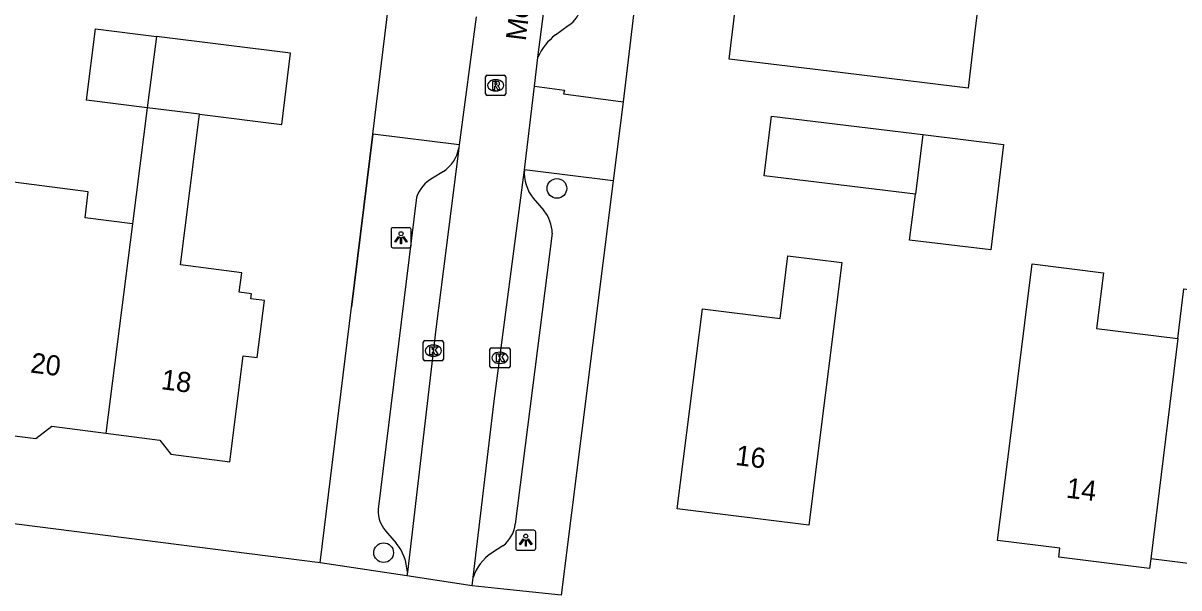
# Model space of a CAD drawing. Extents: x 161258 to 161838, y 380836 to 381727.
# Drawn here: x 161604.4 to 161661.9, y 381360.9 to 381389 of the extents above; entities that cross this region are included whole.
import ezdxf

# ---------------------------------------------------------------- set-up
doc = ezdxf.new("R2010")
doc.units = 0
for name, color, linetype in [('IMGEO_Boom', 7, 'Continuous'), ('IMGEO_Kolk', 7, 'Continuous'), ('IMGEO_Lichtpunt', 7, 'Continuous'), ('IMGEO_Muur', 7, 'Continuous'), ('IMGEO_Openbare_ruimte_label', 7, 'Continuous'), ('IMGEO_Pand', 7, 'Continuous'), ('IMGEO_Pand_nummerreeks', 7, 'Continuous'), ('IMGEO_Rijbaan_lokaal_open', 7, 'Continuous'), ('IMGEO_Rioolput', 7, 'Continuous'), ('IMGEO_Voetpad_open', 7, 'Continuous')]:
    doc.layers.add(name, color=color, linetype=linetype)

msp = doc.modelspace()

# ---------------------------------------------------------------- linework, layer by layer
at = {"layer": 'IMGEO_Boom'}
for centre in [(161630.973, 381380.803), (161622.35, 381362.679)]:
    msp.add_circle(centre, 0.489, dxfattribs=at)
at = {"layer": 'IMGEO_Kolk'}
for p, q in [((161624.324, 381372.305), (161624.324, 381373.157)), ((161624.399, 381373.231), (161625.251, 381373.231)), ((161624.812, 381373.011), (161624.837, 381373.011)), ((161625.325, 381373.157), (161625.325, 381372.305)), ((161627.638, 381371.949), (161627.638, 381372.801)), ((161627.713, 381372.875), (161628.565, 381372.875)), ((161628.639, 381372.801), (161628.639, 381371.949)), ((161625.251, 381372.231), (161624.399, 381372.231)), ((161624.835, 381372.451), (161624.81, 381372.451)), ((161628.149, 381372.095), (161628.124, 381372.095)), ((161628.126, 381372.655), (161628.151, 381372.655)), ((161628.565, 381371.875), (161627.713, 381371.875))]:
    msp.add_line(p, q, dxfattribs=at)
for points in [[(161624.324, 381372.305), (161624.324, 381373.157)], [(161624.399, 381373.231), (161625.251, 381373.231)], [(161624.645, 381372.931), (161624.768, 381372.931), (161624.768, 381372.78), (161624.898, 381372.931), (161625.062, 381372.931), (161624.916, 381372.78), (161625.069, 381372.531), (161624.917, 381372.531), (161624.832, 381372.695), (161624.768, 381372.628), (161624.768, 381372.531), (161624.645, 381372.531), (161624.645, 381372.931)], [(161625.325, 381373.157), (161625.325, 381372.305)], [(161627.638, 381371.949), (161627.638, 381372.801)], [(161627.713, 381372.875), (161628.565, 381372.875)], [(161628.639, 381372.801), (161628.639, 381371.949)], [(161625.251, 381372.231), (161624.399, 381372.231)], [(161627.959, 381372.575), (161628.082, 381372.575), (161628.082, 381372.424), (161628.212, 381372.575), (161628.376, 381372.575), (161628.23, 381372.424), (161628.383, 381372.175), (161628.231, 381372.175), (161628.146, 381372.339), (161628.082, 381372.272), (161628.082, 381372.175), (161627.959, 381372.175), (161627.959, 381372.575)], [(161628.565, 381371.875), (161627.713, 381371.875)]]:
    msp.add_lwpolyline(points, dxfattribs=at)
for centre, start, end in [((161624.401, 381373.155), 91.55205, 178.44795), ((161624.401, 381373.155), 91.55205, 178.44795), ((161625.249, 381373.155), 1.55205, 88.44795), ((161625.249, 381373.155), 1.55205, 88.44795), ((161627.715, 381372.799), 91.55205, 178.44795), ((161627.715, 381372.799), 91.55205, 178.44795), ((161628.563, 381372.799), 1.55205, 88.44795), ((161628.563, 381372.799), 1.55205, 88.44795), ((161624.401, 381372.307), 181.55205, 268.44795), ((161624.401, 381372.307), 181.55205, 268.44795), ((161625.249, 381372.307), 271.55205, 358.44795), ((161625.249, 381372.307), 271.55205, 358.44795), ((161627.715, 381371.951), 181.55205, 268.44795), ((161627.715, 381371.951), 181.55205, 268.44795), ((161628.563, 381371.951), 271.55205, 358.44795), ((161628.563, 381371.951), 271.55205, 358.44795)]:
    msp.add_arc(centre, 0.0765, start, end, dxfattribs=at)
for centre, major_axis, ratio, start_param, end_param in [((161624.811, 381372.731), (-0.387, 0.002), 0.722429, 4.712389, 7.853982), ((161624.836, 381372.731), (-0.39, 0.002), 0.717154, 1.570796, 4.712389), ((161628.125, 381372.375), (-0.387, 0.002), 0.722429, 4.712389, 7.853982), ((161628.15, 381372.375), (-0.39, 0.002), 0.717154, 1.570796, 4.712389)]:
    msp.add_ellipse(centre, major_axis=major_axis, ratio=ratio, start_param=start_param, end_param=end_param, dxfattribs=at)
at = {"layer": 'IMGEO_Lichtpunt'}
for p, q in [((161622.718, 381378.755), (161622.718, 381377.948)), ((161622.718, 381378.755), (161622.718, 381377.948)), ((161623.62, 381378.85), (161622.812, 381378.85)), ((161623.62, 381378.85), (161622.812, 381378.85)), ((161623.714, 381377.948), (161623.714, 381378.755)), ((161623.714, 381377.948), (161623.714, 381378.755)), ((161622.812, 381377.854), (161623.62, 381377.854)), ((161622.812, 381377.854), (161623.62, 381377.854)), ((161628.926, 381363.704), (161628.926, 381362.897)), ((161628.926, 381363.704), (161628.926, 381362.897)), ((161629.828, 381363.799), (161629.02, 381363.799)), ((161629.828, 381363.799), (161629.02, 381363.799)), ((161629.922, 381362.897), (161629.922, 381363.704)), ((161629.922, 381362.897), (161629.922, 381363.704)), ((161629.02, 381362.803), (161629.828, 381362.803)), ((161629.02, 381362.803), (161629.828, 381362.803))]:
    msp.add_line(p, q, dxfattribs=at)
for points in [[(161623.092, 381378.419), (161623.131, 381378.391), (161622.943, 381378.129), (161622.905, 381378.156), (161623.092, 381378.419)], [(161623.304, 381378.391), (161623.342, 381378.418), (161623.529, 381378.156), (161623.49, 381378.128), (161623.304, 381378.391)], [(161623.194, 381378.371), (161623.241, 381378.371), (161623.241, 381378.049), (161623.194, 381378.049), (161623.194, 381378.371)], [(161629.3, 381363.368), (161629.339, 381363.34), (161629.151, 381363.078), (161629.113, 381363.105), (161629.3, 381363.368)], [(161629.402, 381363.32), (161629.449, 381363.32), (161629.449, 381362.998), (161629.402, 381362.998), (161629.402, 381363.32)], [(161629.512, 381363.34), (161629.55, 381363.367), (161629.737, 381363.105), (161629.698, 381363.077), (161629.512, 381363.34)]]:
    msp.add_lwpolyline(points, dxfattribs=at)
for centre in [(161623.217, 381378.553), (161629.425, 381363.502)]:
    msp.add_circle(centre, 0.0994, dxfattribs=at)
for centre, start, end in [((161622.812, 381378.755), 90, 180), ((161622.812, 381378.755), 90, 180), ((161623.62, 381378.755), 0, 90), ((161623.62, 381378.755), 0, 90), ((161622.812, 381377.948), 180, 270), ((161622.812, 381377.948), 180, 270), ((161623.62, 381377.948), 270, 0), ((161623.62, 381377.948), 270, 360), ((161629.02, 381363.704), 90, 180), ((161629.02, 381363.704), 90, 180), ((161629.828, 381363.704), 0, 90), ((161629.828, 381363.704), 0, 90), ((161629.02, 381362.897), 180, 270), ((161629.02, 381362.897), 180, 270), ((161629.828, 381362.897), 270, 0), ((161629.828, 381362.897), 270, 360)]:
    msp.add_arc(centre, 0.0946, start, end, dxfattribs=at)
at = {"layer": 'IMGEO_Muur'}
msp.add_lwpolyline([(161621.814, 381383.511), (161620.757, 381374.9)], dxfattribs=at)
at = {"layer": 'IMGEO_Pand'}
for points in [[(161652.148, 381391.662), (161651.795, 381388.769), (161651.432, 381385.79), (161644.514, 381386.633), (161639.55, 381387.238), (161640.266, 381393.111)], [(161610.59, 381384.821), (161607.568, 381385.197), (161608.01, 381388.751), (161611.043, 381388.373)], [(161611.043, 381388.373), (161610.59, 381384.821)], [(161613.194, 381384.497), (161617.277, 381383.989), (161617.719, 381387.542), (161611.043, 381388.373)], [(161610.59, 381384.821), (161609.854, 381379.048)], [(161613.194, 381384.497), (161610.59, 381384.821)], [(161608.525, 381368.628), (161611.209, 381368.286), (161611.76, 381367.574), (161614.692, 381367.201), (161615.363, 381372.479), (161616.061, 381372.39), (161616.422, 381375.228), (161615.743, 381375.315), (161615.775, 381375.563), (161615.167, 381375.64), (161615.29, 381376.61), (161612.242, 381376.998), (161612.46, 381378.716), (161613.194, 381384.497)], [(161648.815, 381380.521), (161641.286, 381381.438), (161641.648, 381384.402), (161649.176, 381383.485)], [(161649.176, 381383.485), (161653.203, 381382.992), (161652.564, 381377.744), (161648.516, 381378.237), (161648.815, 381380.521)], [(161649.176, 381383.485), (161648.815, 381380.521)], [(161609.854, 381379.048), (161607.5, 381379.347), (161607.655, 381380.635), (161603.936, 381381.109), (161603.542, 381378.017), (161603.416, 381377.03), (161602.922, 381377.093), (161602.493, 381373.724), (161601.862, 381368.764), (161605.051, 381368.358), (161605.841, 381368.969), (161608.525, 381368.628)], [(161609.854, 381379.048), (161608.525, 381368.628)], [(161643.508, 381364.046), (161636.964, 381364.868), (161638.215, 381374.816), (161642.075, 381374.33), (161642.468, 381377.453), (161645.151, 381377.115), (161643.508, 381364.046)], [(161660.531, 381362.376), (161660.47, 381361.885), (161655.947, 381362.454), (161656.003, 381362.9), (161652.899, 381363.29), (161653.522, 381368.251), (161654.621, 381377.046), (161658.181, 381376.613), (161657.832, 381373.841), (161661.873, 381373.334)], [(161661.873, 381373.334), (161662.175, 381375.804), (161664.964, 381375.453), (161664.351, 381370.574), (161669.196, 381369.965), (161668.698, 381366.006), (161670.713, 381365.753), (161670.136, 381361.169), (161667.027, 381361.559), (161660.531, 381362.376)], [(161661.873, 381373.334), (161660.531, 381362.376)]]:
    msp.add_lwpolyline(points, dxfattribs=at)
at = {"layer": 'IMGEO_Rijbaan_lokaal_open'}
for points in [[(161630.024, 381387.329), (161631.028, 381395.148), (161632.729, 381408.516)], [(161626.958, 381389.351), (161626.112, 381382.98)], [(161629.854, 381385.901), (161630.024, 381387.329)], [(161629.358, 381381.739), (161629.854, 381385.901)], [(161626.09, 381382.805), (161624.952, 381373.802), (161623.53, 381361.715)], [(161626.112, 381382.98), (161626.09, 381382.805)], [(161626.812, 381361.453), (161627.856, 381370.215), (161629.358, 381381.739)], [(161619.194, 381362.168), (161601.597, 381364.408)], [(161623.507, 381361.52), (161619.194, 381362.168)], [(161623.53, 381361.715), (161623.507, 381361.52)], [(161626.762, 381361.028), (161623.507, 381361.52)], [(161626.762, 381361.028), (161626.779, 381361.172), (161626.812, 381361.453)], [(161631.183, 381360.562), (161628.33, 381360.863), (161626.762, 381361.028)]]:
    msp.add_lwpolyline(points, dxfattribs=at)
at = {"layer": 'IMGEO_Rioolput'}
for p, q in [((161627.425, 381385.508), (161627.425, 381386.36)), ((161627.5, 381386.434), (161628.352, 381386.434)), ((161627.913, 381386.214), (161627.938, 381386.214)), ((161628.426, 381386.36), (161628.426, 381385.508)), ((161628.352, 381385.434), (161627.5, 381385.434)), ((161627.936, 381385.654), (161627.911, 381385.654))]:
    msp.add_line(p, q, dxfattribs=at)
for points in [[(161627.425, 381385.508), (161627.425, 381386.36)], [(161627.5, 381386.434), (161628.352, 381386.434)], [(161628.014, 381386.132), (161627.762, 381386.134), (161627.762, 381385.734)], [(161627.762, 381385.734), (161627.886, 381385.734), (161627.886, 381385.896), (161627.897, 381385.896)], [(161627.94, 381386.053), (161627.886, 381386.053), (161627.886, 381385.972)], [(161627.886, 381385.972), (161627.938, 381385.972)], [(161628.426, 381386.36), (161628.426, 381385.508)], [(161628.352, 381385.434), (161627.5, 381385.434)], [(161627.944, 381385.867), (161628.015, 381385.734), (161628.155, 381385.734), (161628.09, 381385.86)]]:
    msp.add_lwpolyline(points, dxfattribs=at)
for centre, radius, start, end in [((161627.502, 381386.358), 0.0765, 91.55205, 178.44795), ((161627.502, 381386.358), 0.0765, 91.55205, 178.44795), ((161627.896, 381385.843), 0.0533, 26.02933, 88.69889), ((161627.922, 381386.161), 0.19, 274.7715, 282.96867), ((161627.946, 381385.957), 0.0964, 77.00612, 93.18647), ((161627.96, 381386.014), 0.0378, 276.66336, 79.67722), ((161628.013, 381386.022), 0.109, 350.36119, 89.41601), ((161628.011, 381386.022), 0.112, 277.58423, 350.98172), ((161627.995, 381385.807), 0.108, 29.51342, 73.79051), ((161628.35, 381386.358), 0.0765, 1.55205, 88.44795), ((161628.35, 381386.358), 0.0765, 1.55205, 88.44795), ((161627.502, 381385.51), 0.0765, 181.55205, 268.44795), ((161627.502, 381385.51), 0.0765, 181.55205, 268.44795), ((161628.35, 381385.51), 0.0765, 271.55205, 358.44795), ((161628.35, 381385.51), 0.0765, 271.55205, 358.44795)]:
    msp.add_arc(centre, radius, start, end, dxfattribs=at)
for centre, major_axis, ratio, start_param, end_param in [((161627.912, 381385.934), (-0.387, 0.002), 0.722429, 4.712389, 7.853982), ((161627.937, 381385.934), (-0.39, 0.002), 0.717154, 1.570796, 4.712389)]:
    msp.add_ellipse(centre, major_axis=major_axis, ratio=ratio, start_param=start_param, end_param=end_param, dxfattribs=at)
at = {"layer": 'IMGEO_Voetpad_open'}
for points in [[(161632.557, 381433.385), (161638.239, 381417.444), (161637.547, 381412.742), (161634.273, 381385.117)], [(161621.814, 381383.511), (161622.597, 381389.891)], [(161630.896, 381388.447), (161631.532, 381388.914)], [(161629.854, 381385.901), (161631.355, 381385.691), (161631.303, 381385.513), (161634.273, 381385.117)], [(161634.273, 381385.117), (161633.778, 381381.183)], [(161619.194, 381362.168), (161620.757, 381374.9), (161621.814, 381383.511)], [(161626.112, 381382.98), (161621.814, 381383.511)], [(161625.323, 381381.65), (161624.788, 381381.321)], [(161633.778, 381381.183), (161629.358, 381381.739)], [(161633.778, 381381.183), (161631.183, 381360.562)], [(161623.985, 381380.359), (161622.085, 381364.84)], [(161629.798, 381380.326), (161630.329, 381379.702)], [(161630.743, 381378.584), (161628.898, 381364.105)], [(161622.55, 381363.645), (161622.98, 381363.161)], [(161628.285, 381363.016), (161627.716, 381362.653)]]:
    msp.add_lwpolyline(points, dxfattribs=at)
for centre, radius, start, end in [((161630.92, 381389.992), 1.239, 299.57212, 357.04909), ((161632.826, 381386.043), 3.083, 128.75236, 155.34173), ((161624.386, 381383.105), 1.731, 302.79882, 350.02735), ((161625.592, 381379.833), 1.691, 118.40045, 161.89474), ((161631.279, 381381.562), 1.929, 174.74121, 219.85136), ((161628.825, 381378.51), 1.919, 2.22441, 38.41519), ((161623.599, 381364.741), 1.517, 176.25885, 226.2653), ((161627.292, 381364.292), 1.617, 307.89542, 353.35411), ((161620.999, 381361.58), 2.535, 3.05764, 38.59194), ((161628.936, 381360.793), 2.225, 123.27167, 162.74447)]:
    msp.add_arc(centre, radius, start, end, dxfattribs=at)

# ---------------------------------------------------------------- texts
at = {"layer": 'IMGEO_Openbare_ruimte_label'}
msp.add_text('Melati van Javalaan', height=1, rotation=82.76127, dxfattribs=at).set_placement((161629.419, 381388.115))
at = {"layer": 'IMGEO_Pand_nummerreeks'}
for s, rotation, p in [('20', 352.74891, (161604.74, 381371.65)), ('18', 352.74635, (161611.24, 381370.822)), ('16', 352.8405, (161639.82, 381367.049)), ('14', 353.17034, (161656.284, 381365.422))]:
    msp.add_text(s, height=1, rotation=rotation, dxfattribs=at).set_placement(p)

doc.saveas('drawing.dxf')
